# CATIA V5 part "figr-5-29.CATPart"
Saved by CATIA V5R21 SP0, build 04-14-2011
Part number: Part1
Bounding box of the stored display mesh (mm): x -100 to 100, y -100 to 100, z 0 to 57
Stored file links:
  D:\CATIA V5R21 E-RESOURCES\CATIA-V5R21\catia-v5r21-prt\c05-catia-v5r20-prt\catia-v5r21-figr-5-29.CATPart
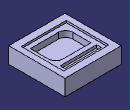
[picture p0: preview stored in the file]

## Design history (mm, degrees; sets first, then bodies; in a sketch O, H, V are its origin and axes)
Body1 (main body)
  Sketch1 on xy-plane, origin (0, 0, 0), H (1, 0, 0), V (0, 1, 0)
    line L1 (-100, 100) -> (100, 100)
    line L2 (100, 100) -> (100, -100)
    line L3 (100, -100) -> (-100, -100)
    line L4 (-100, -100) -> (-100, 100)
    axis line L5 (100, -100) -> (-100, 100)
    length L3 = 200
    length L2 = 200
    horizontal: L1 H, L3 H
    vertical: L2 V, L4 V
    midpoint: L5 O
  Pad1: profile Sketch1, direction (0, 0, 1), length 57
  Sketch2 on face of Pad1, origin (0, 0, 57), H (1, 0, 0), V (0, 1, 0)
    line L1 (-80.0557, 75.5465) -> (80.0557, 75.5465)
    line L2 (80.0557, 75.5465) -> (80.0557, -75.5465)
    line L3 (80.0557, -75.5465) -> (-80.0557, -75.5465)
    line L4 (-80.0557, -75.5465) -> (-80.0557, 75.5465)
    axis line L5 (80.0557, -75.5465) -> (-80.0557, 75.5465)
    line L6 (-62.1297, 30.1268) -> (-62.1297, -34.9955)
    arc A1 centre (-37.2362, -34.9955) radius 24.8935 from (-62.1297, -34.9955) to (-37.2362, -59.889) ccw
    line L7 (-37.2362, -59.889) -> (63.4636, -59.889)
    point P9 (63.4636, -59.889)
    line L8 (63.4636, -59.889) -> (63.4636, 3.0218)
    arc A2 centre (36.331, 3.0218) radius 27.1326 from (63.4636, 3.0218) to (35.1072, 30.1268) ccw
    line L9 (35.1072, 30.1268) -> (-62.1297, 30.1268)
    point P13 (-66.3387, 62.6022)
    line L10 (-66.3387, 62.6022) -> (63.4636, 62.6022)
    line L11 (63.4636, 62.6022) -> (63.4636, 45.9932)
    line L12 (63.4636, 45.9932) -> (-66.3387, 45.9932)
    line L13 (-66.3387, 45.9932) -> (-66.3387, 62.6022)
    point P15 (63.4636, 45.9932)
    horizontal: L1 H, L3 H, L9 H, L10 H, L12 H
    vertical: L2 V, L4 V, L6 V, L8 V, L11 V, L13 V
    midpoint: O L5
    tangency: A1 L6, L7 A1, A2 L5, A2 L8
    coincidence: P9 L5, P13 L5, P15 L8
  MultiPocket1: profile Sketch2, domains (length 17; length 28; length 7)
